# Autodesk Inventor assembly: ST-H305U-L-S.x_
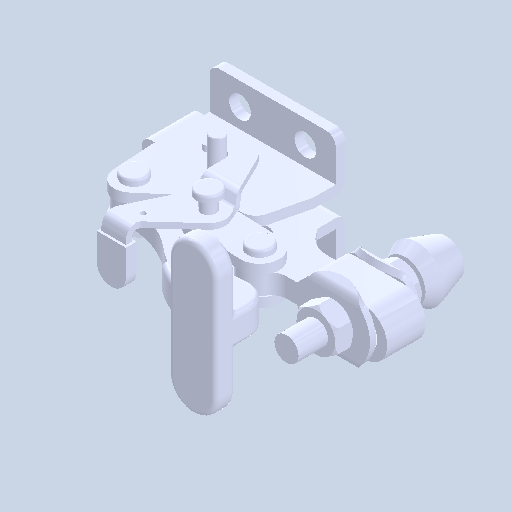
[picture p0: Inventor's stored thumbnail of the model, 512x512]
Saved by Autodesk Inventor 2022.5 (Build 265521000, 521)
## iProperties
Created: 2024-07
Part Number: ST-H305U-L-S.x_
Document SubType Name: Assembly
Designer: ImaoCorp
Author: ImaoCorp
Sending System: SOLIDWORKS 2022-2022290
MC: AMD64
MC_MODEL: Intel64 Family 6 Model 60 Stepping 3, GenuineIntel
OS: Windows_NT
FRU: Parasolid Version 33.1, build 260,  4-25-2022
FORMAT: text
GUISE: transmit
KEY: FILEST-H305U-L-S.x_t
DATE: Mon Jul 29 10:02:34 2024
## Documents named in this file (8)
- X:\14_SW2022-Inv2022\07_2024-10新製品(WHS)\OTC_データ\s\st-h305u-l-s\ST-H305U-L-S.x_.iam
- X:\14_SW2022-Inv2022\07_2024-10新製品(WHS)\OTC_データ\s\st-h305u-l-s\ST-H305U-L-S_01.ipt
- X:\14_SW2022-Inv2022\07_2024-10新製品(WHS)\OTC_データ\s\st-h305u-l-s\ST-H305U-L-S_02.ipt
- X:\14_SW2022-Inv2022\07_2024-10新製品(WHS)\OTC_データ\s\st-h305u-l-s\ST-H305U-L-S_03.ipt
- X:\14_SW2022-Inv2022\07_2024-10新製品(WHS)\OTC_データ\s\st-h305u-l-s\ST-H305U-L-S_04.ipt
- X:\14_SW2022-Inv2022\07_2024-10新製品(WHS)\OTC_データ\s\st-h305u-l-s\ST-H305U-L-S_05.ipt
- X:\14_SW2022-Inv2022\07_2024-10新製品(WHS)\OTC_データ\s\st-h305u-l-s\ST-H305U-L-S_06.ipt
- X:\14_SW2022-Inv2022\07_2024-10新製品(WHS)\OTC_データ\s\st-h305u-l-s\ST-H305U-L-S_07.ipt
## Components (7 placed, 7 different names)
1. ST-H305U-L-S_01
2. ST-H305U-L-S_02
3. ST-H305U-L-S_03
4. ST-H305U-L-S_04
5. ST-H305U-L-S_05
6. ST-H305U-L-S_06
7. ST-H305U-L-S_07
